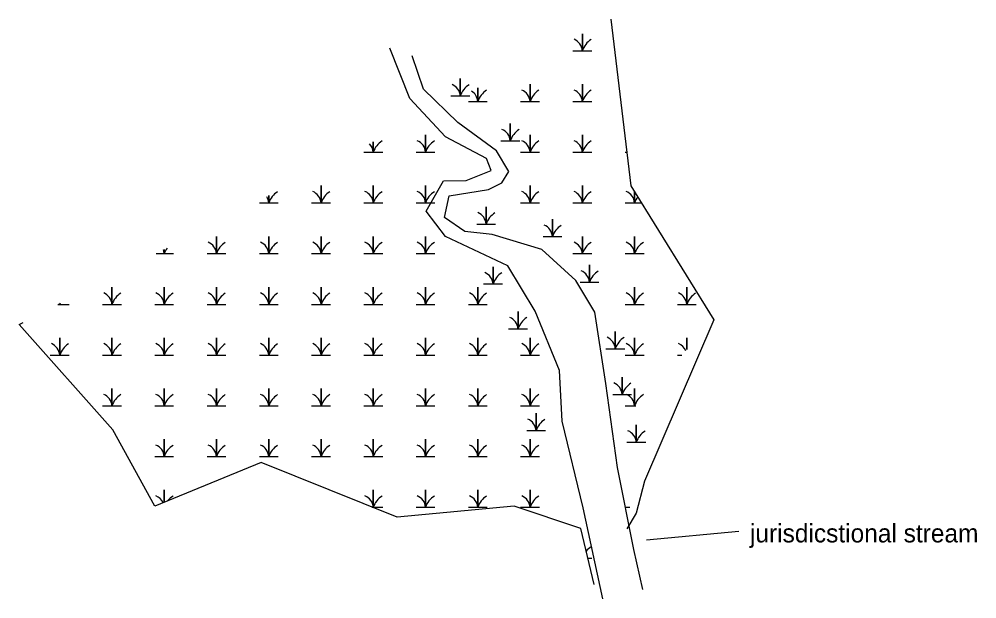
# Model space of a CAD drawing. Extents: x 2171061 to 2188174, y 801741 to 821647.
# Drawn here: x 2177074.5 to 2177361.5, y 807942.3 to 808115.8 of the extents above; entities that cross this region are included whole.
import ezdxf

# ---------------------------------------------------------------- set-up
doc = ezdxf.new("R2010")
doc.units = 0
doc.layers.add('Exist Environmental Wetland Boundary', color=7, linetype='Continuous')
doc.layers.add('Exist Hydro Jurisdictional Stream or Body of Water Mitigable', color=7, linetype='Continuous')

msp = doc.modelspace()

# ---------------------------------------------------------------- linework, layer by layer
at = {"layer": 'Exist Environmental Wetland Boundary'}
for points in [[(2177251.87, 808115.78), (2177257.81, 808065.93), (2177282.69, 808025.78), (2177261.9, 807977.45), (2177259.44, 807967.95), (2177256.66, 807963.24)], [(2177240.47, 808106.33), (2177243.29, 808106.33), (2177243.29, 808111.35)], [(2177243.29, 808111.35), (2177243.29, 808106.33), (2177246.11, 808106.33)], [(2177203.91, 808092.79), (2177206.73, 808092.79), (2177206.73, 808097.97), (2177206.73, 808092.79), (2177209.55, 808092.79)], [(2177209.15, 808091.14), (2177211.97, 808091.14), (2177211.97, 808095.22)], [(2177211.97, 808095.22), (2177211.97, 808091.14), (2177214.79, 808091.14)], [(2177224.81, 808091.14), (2177227.63, 808091.14), (2177227.63, 808096.32), (2177227.63, 808091.14), (2177230.45, 808091.14)], [(2177240.47, 808091.14), (2177243.29, 808091.14), (2177243.29, 808096.32), (2177243.29, 808091.14), (2177246.11, 808091.14)], [(2177218.87, 808079.36), (2177221.69, 808079.36), (2177221.69, 808084.54), (2177221.69, 808079.36), (2177224.52, 808079.36)], [(2177193.49, 808075.96), (2177196.31, 808075.96), (2177196.31, 808081.14), (2177196.31, 808075.96), (2177199.13, 808075.96)], [(2177224.81, 808075.96), (2177227.63, 808075.96), (2177227.63, 808081.14), (2177227.63, 808075.96), (2177230.45, 808075.96)], [(2177240.47, 808075.96), (2177243.29, 808075.96), (2177243.29, 808081.14), (2177243.29, 808075.96), (2177246.11, 808075.96)], [(2177177.83, 808075.96), (2177180.65, 808075.96), (2177180.65, 808079.08)], [(2177180.65, 808079.08), (2177180.65, 808075.96), (2177183.47, 808075.96)], [(2177256.13, 808075.96), (2177256.61, 808075.96)], [(2177162.17, 808060.78), (2177164.99, 808060.78), (2177164.99, 808065.95), (2177164.99, 808060.78), (2177167.81, 808060.78)], [(2177177.83, 808060.78), (2177180.65, 808060.78), (2177180.65, 808065.95), (2177180.65, 808060.78), (2177183.47, 808060.78)], [(2177193.49, 808060.78), (2177196.31, 808060.78), (2177196.31, 808065.95), (2177196.31, 808060.78), (2177199.13, 808060.78)], [(2177224.81, 808060.78), (2177227.63, 808060.78), (2177227.63, 808065.95), (2177227.63, 808060.78), (2177230.45, 808060.78)], [(2177240.47, 808060.78), (2177243.29, 808060.78), (2177243.29, 808065.95), (2177243.29, 808060.78), (2177246.11, 808060.78)], [(2177146.51, 808060.78), (2177149.33, 808060.78), (2177149.33, 808062.95)], [(2177149.33, 808062.95), (2177149.33, 808060.78), (2177152.15, 808060.78)], [(2177256.13, 808060.78), (2177258.95, 808060.78), (2177258.95, 808064.09)], [(2177258.95, 808064.09), (2177258.95, 808060.78), (2177261, 808060.78)], [(2177211.67, 808054.46), (2177214.49, 808054.46), (2177214.49, 808059.64), (2177214.49, 808054.46), (2177217.31, 808054.46)], [(2177231.52, 808050.71), (2177234.34, 808050.71), (2177234.34, 808055.88), (2177234.34, 808050.71), (2177237.16, 808050.71)], [(2177130.85, 808045.59), (2177133.67, 808045.59), (2177133.67, 808050.77), (2177133.67, 808045.59), (2177136.49, 808045.59)], [(2177146.51, 808045.59), (2177149.33, 808045.59), (2177149.33, 808050.77), (2177149.33, 808045.59), (2177152.15, 808045.59)], [(2177162.17, 808045.59), (2177164.99, 808045.59), (2177164.99, 808050.77), (2177164.99, 808045.59), (2177167.81, 808045.59)], [(2177177.83, 808045.59), (2177180.65, 808045.59), (2177180.65, 808050.77), (2177180.65, 808045.59), (2177183.47, 808045.59)], [(2177193.49, 808045.59), (2177196.31, 808045.59), (2177196.31, 808050.77), (2177196.31, 808045.59), (2177199.13, 808045.59)], [(2177240.47, 808045.59), (2177243.29, 808045.59), (2177243.29, 808050.77), (2177243.29, 808045.59), (2177246.11, 808045.59)], [(2177256.13, 808045.59), (2177258.95, 808045.59), (2177258.95, 808050.77), (2177258.95, 808045.59), (2177261.77, 808045.59)], [(2177115.64, 808045.59), (2177118.01, 808045.59), (2177118.01, 808046.82)], [(2177118.01, 808046.82), (2177118.01, 808045.59), (2177120.84, 808045.59)], [(2177213.71, 808036.51), (2177216.53, 808036.51), (2177216.53, 808041.69), (2177216.53, 808036.51), (2177219.36, 808036.51)], [(2177242.61, 808037.02), (2177245.43, 808037.02), (2177245.43, 808042.2), (2177245.43, 808037.02), (2177248.25, 808037.02)], [(2177099.53, 808030.41), (2177102.35, 808030.41), (2177102.35, 808035.59), (2177102.35, 808030.41), (2177105.18, 808030.41)], [(2177115.19, 808030.41), (2177118.01, 808030.41), (2177118.01, 808035.59), (2177118.01, 808030.41), (2177120.84, 808030.41)], [(2177130.85, 808030.41), (2177133.67, 808030.41), (2177133.67, 808035.59), (2177133.67, 808030.41), (2177136.49, 808030.41)], [(2177146.51, 808030.41), (2177149.33, 808030.41), (2177149.33, 808035.59), (2177149.33, 808030.41), (2177152.15, 808030.41)], [(2177162.17, 808030.41), (2177164.99, 808030.41), (2177164.99, 808035.59), (2177164.99, 808030.41), (2177167.81, 808030.41)], [(2177177.83, 808030.41), (2177180.65, 808030.41), (2177180.65, 808035.59), (2177180.65, 808030.41), (2177183.47, 808030.41)], [(2177193.49, 808030.41), (2177196.31, 808030.41), (2177196.31, 808035.59), (2177196.31, 808030.41), (2177199.13, 808030.41)], [(2177209.15, 808030.41), (2177211.97, 808030.41), (2177211.97, 808035.59), (2177211.97, 808030.41), (2177214.79, 808030.41)], [(2177256.13, 808030.41), (2177258.95, 808030.41), (2177258.95, 808035.59), (2177258.95, 808030.41), (2177261.77, 808030.41)], [(2177271.79, 808030.41), (2177274.61, 808030.41), (2177274.61, 808035.59), (2177274.61, 808030.41), (2177277.43, 808030.41)], [(2177086.16, 808030.41), (2177086.69, 808030.41), (2177086.69, 808030.68)], [(2177086.69, 808030.68), (2177086.69, 808030.41), (2177089.52, 808030.41)], [(2177221.19, 808023.08), (2177224.02, 808023.08), (2177224.02, 808028.26), (2177224.02, 808023.08), (2177226.84, 808023.08)], [(2177246.81, 807946.58), (2177242.88, 807963.33), (2177222.88, 807970.03), (2177187.78, 807966.67), (2177147.02, 807983.05), (2177115.16, 807969.99), (2177102.58, 807992.82), (2177074.55, 808024.42), (2177075.7, 808025.02)], [(2177250.35, 808017.15), (2177253.17, 808017.15), (2177253.17, 808022.32), (2177253.17, 808017.15), (2177256, 808017.15)], [(2177083.87, 808015.22), (2177086.69, 808015.22), (2177086.69, 808020.4), (2177086.69, 808015.22), (2177089.52, 808015.22)], [(2177099.53, 808015.22), (2177102.35, 808015.22), (2177102.35, 808020.4), (2177102.35, 808015.22), (2177105.18, 808015.22)], [(2177115.19, 808015.22), (2177118.01, 808015.22), (2177118.01, 808020.4), (2177118.01, 808015.22), (2177120.84, 808015.22)], [(2177130.85, 808015.22), (2177133.67, 808015.22), (2177133.67, 808020.4), (2177133.67, 808015.22), (2177136.49, 808015.22)], [(2177146.51, 808015.22), (2177149.33, 808015.22), (2177149.33, 808020.4), (2177149.33, 808015.22), (2177152.15, 808015.22)], [(2177162.17, 808015.22), (2177164.99, 808015.22), (2177164.99, 808020.4), (2177164.99, 808015.22), (2177167.81, 808015.22)], [(2177177.83, 808015.22), (2177180.65, 808015.22), (2177180.65, 808020.4), (2177180.65, 808015.22), (2177183.47, 808015.22)], [(2177193.49, 808015.22), (2177196.31, 808015.22), (2177196.31, 808020.4), (2177196.31, 808015.22), (2177199.13, 808015.22)], [(2177209.15, 808015.22), (2177211.97, 808015.22), (2177211.97, 808020.4), (2177211.97, 808015.22), (2177214.79, 808015.22)], [(2177224.81, 808015.22), (2177227.63, 808015.22), (2177227.63, 808020.4), (2177227.63, 808015.22), (2177230.45, 808015.22)], [(2177256.13, 808015.22), (2177258.95, 808015.22), (2177258.95, 808020.4), (2177258.95, 808015.22), (2177261.77, 808015.22)], [(2177274.61, 808016.88), (2177274.61, 808020.4), (2177274.61, 808016.88)], [(2177271.79, 808015.22), (2177273.1, 808015.22)], [(2177252.42, 808003.46), (2177255.24, 808003.46), (2177255.24, 808008.64), (2177255.24, 808003.46), (2177258.06, 808003.46)], [(2177099.53, 808000.04), (2177102.35, 808000.04), (2177102.35, 808005.22), (2177102.35, 808000.04), (2177105.18, 808000.04)], [(2177115.19, 808000.04), (2177118.01, 808000.04), (2177118.01, 808005.22), (2177118.01, 808000.04), (2177120.84, 808000.04)], [(2177130.85, 808000.04), (2177133.67, 808000.04), (2177133.67, 808005.22), (2177133.67, 808000.04), (2177136.49, 808000.04)], [(2177146.51, 808000.04), (2177149.33, 808000.04), (2177149.33, 808005.22), (2177149.33, 808000.04), (2177152.15, 808000.04)], [(2177162.17, 808000.04), (2177164.99, 808000.04), (2177164.99, 808005.22), (2177164.99, 808000.04), (2177167.81, 808000.04)], [(2177177.83, 808000.04), (2177180.65, 808000.04), (2177180.65, 808005.22), (2177180.65, 808000.04), (2177183.47, 808000.04)], [(2177193.49, 808000.04), (2177196.31, 808000.04), (2177196.31, 808005.22), (2177196.31, 808000.04), (2177199.13, 808000.04)], [(2177209.15, 808000.04), (2177211.97, 808000.04), (2177211.97, 808005.22), (2177211.97, 808000.04), (2177214.79, 808000.04)], [(2177224.81, 808000.04), (2177227.63, 808000.04), (2177227.63, 808005.22), (2177227.63, 808000.04), (2177230.45, 808000.04)], [(2177256.13, 808000.04), (2177258.95, 808000.04), (2177258.95, 808005.22), (2177258.95, 808000.04), (2177259.3, 808000.04)], [(2177226.61, 807992.62), (2177229.44, 807992.62), (2177229.44, 807997.8), (2177229.44, 807992.62), (2177232.26, 807992.62)], [(2177256.63, 807989.14), (2177259.45, 807989.14), (2177259.45, 807994.32), (2177259.45, 807989.14), (2177262.28, 807989.14)], [(2177115.19, 807984.86), (2177118.01, 807984.86), (2177118.01, 807990.03), (2177118.01, 807984.86), (2177120.84, 807984.86)], [(2177130.85, 807984.86), (2177133.67, 807984.86), (2177133.67, 807990.03), (2177133.67, 807984.86), (2177136.49, 807984.86)], [(2177146.51, 807984.86), (2177149.33, 807984.86), (2177149.33, 807990.03), (2177149.33, 807984.86), (2177152.15, 807984.86)], [(2177162.17, 807984.86), (2177164.99, 807984.86), (2177164.99, 807990.03), (2177164.99, 807984.86), (2177167.81, 807984.86)], [(2177177.83, 807984.86), (2177180.65, 807984.86), (2177180.65, 807990.03), (2177180.65, 807984.86), (2177183.47, 807984.86)], [(2177193.49, 807984.86), (2177196.31, 807984.86), (2177196.31, 807990.03), (2177196.31, 807984.86), (2177199.13, 807984.86)], [(2177209.15, 807984.86), (2177211.97, 807984.86), (2177211.97, 807990.03), (2177211.97, 807984.86), (2177214.79, 807984.86)], [(2177224.81, 807984.86), (2177227.63, 807984.86), (2177227.63, 807990.03), (2177227.63, 807984.86), (2177230.45, 807984.86)], [(2177118.01, 807971.16), (2177118.01, 807974.85), (2177118.01, 807971.16)], [(2177180.32, 807969.67), (2177180.65, 807969.67), (2177180.65, 807974.85), (2177180.65, 807969.67), (2177183.47, 807969.67)], [(2177193.49, 807969.67), (2177196.31, 807969.67), (2177196.31, 807974.85), (2177196.31, 807969.67), (2177199.13, 807969.67)], [(2177209.15, 807969.67), (2177211.97, 807969.67), (2177211.97, 807974.85), (2177211.97, 807969.67), (2177214.79, 807969.67)], [(2177224.81, 807969.67), (2177227.63, 807969.67), (2177227.63, 807974.85), (2177227.63, 807969.67), (2177230.45, 807969.67)], [(2177256.13, 807969.67), (2177257.53, 807969.67)], [(2177244.96, 807954.49), (2177246.11, 807954.49)]]:
    msp.add_lwpolyline(points, dxfattribs=at)
for centre, radius, start, end in [((2177239.26, 808106.04), 4.03, 4.1403, 67.535), ((2177249.27, 808104.34), 6.31, 122.1274, 161.6222), ((2177202.7, 808092.5), 4.03, 4.1403, 67.535), ((2177212.71, 808090.8), 6.31, 122.1274, 161.6222), ((2177207.95, 808090.85), 4.03, 4.1403, 57.6127), ((2177217.95, 808089.15), 6.31, 122.1274, 161.6222), ((2177223.6, 808090.85), 4.03, 4.1403, 67.535), ((2177233.61, 808089.15), 6.31, 122.1274, 161.6222), ((2177239.26, 808090.85), 4.03, 4.1403, 67.535), ((2177249.27, 808089.15), 6.31, 122.1274, 161.6222), ((2177217.67, 808079.07), 4.03, 4.1403, 67.535), ((2177227.68, 808077.38), 6.31, 122.1274, 161.6222), ((2177176.63, 808075.67), 4.03, 4.1403, 44.4732), ((2177186.64, 808073.97), 6.31, 122.1274, 161.6222), ((2177192.29, 808075.67), 4.03, 4.1403, 67.535), ((2177202.3, 808073.97), 6.31, 122.1274, 161.6222), ((2177223.6, 808075.67), 4.03, 4.1403, 67.535), ((2177233.61, 808073.97), 6.31, 122.1274, 161.6222), ((2177239.26, 808075.67), 4.03, 4.1403, 67.535), ((2177249.27, 808073.97), 6.31, 122.1274, 161.6222), ((2177145.31, 808060.48), 4.03, 4.1403, 32.2245), ((2177155.32, 808058.79), 6.31, 122.1274, 161.6222), ((2177160.97, 808060.48), 4.03, 4.1403, 67.535), ((2177170.98, 808058.79), 6.31, 122.1274, 161.6222), ((2177176.63, 808060.48), 4.03, 4.1403, 67.535), ((2177186.64, 808058.79), 6.31, 122.1274, 161.6222), ((2177192.29, 808060.48), 4.03, 4.1403, 67.535), ((2177202.3, 808058.79), 6.31, 122.1274, 161.6222), ((2177223.6, 808060.48), 4.03, 4.1403, 67.535), ((2177233.61, 808058.79), 6.31, 122.1274, 161.6222), ((2177239.26, 808060.48), 4.03, 4.1403, 67.535), ((2177249.27, 808058.79), 6.31, 122.1274, 161.6222), ((2177254.92, 808060.48), 4.03, 4.1403, 67.535), ((2177264.93, 808058.79), 6.31, 143.128, 161.6222), ((2177210.46, 808054.17), 4.03, 4.1403, 67.535), ((2177220.47, 808052.47), 6.31, 122.1274, 161.6222), ((2177230.31, 808050.42), 4.03, 4.1403, 67.535), ((2177240.32, 808048.72), 6.31, 122.1274, 161.6222), ((2177129.65, 808045.3), 4.03, 4.1403, 67.535), ((2177139.66, 808043.6), 6.31, 122.1274, 161.6222), ((2177145.31, 808045.3), 4.03, 4.1403, 67.535), ((2177155.32, 808043.6), 6.31, 122.1274, 161.6222), ((2177160.97, 808045.3), 4.03, 4.1403, 67.535), ((2177170.98, 808043.6), 6.31, 122.1274, 161.6222), ((2177176.63, 808045.3), 4.03, 4.1403, 67.535), ((2177186.64, 808043.6), 6.31, 122.1274, 161.6222), ((2177192.29, 808045.3), 4.03, 4.1403, 67.535), ((2177202.3, 808043.6), 6.31, 122.1274, 161.6222), ((2177239.26, 808045.3), 4.03, 4.1403, 67.535), ((2177249.27, 808043.6), 6.31, 122.1274, 161.6222), ((2177254.92, 808045.3), 4.03, 4.1403, 67.535), ((2177264.93, 808043.6), 6.31, 122.1274, 161.6222), ((2177113.99, 808045.3), 4.03, 4.1403, 20.2035), ((2177124, 808043.6), 6.31, 144.6947, 161.6222), ((2177212.51, 808036.22), 4.03, 4.1403, 67.535), ((2177222.52, 808034.52), 6.31, 122.1274, 161.6222), ((2177241.41, 808036.73), 4.03, 4.1403, 67.535), ((2177251.42, 808035.04), 6.31, 122.1274, 161.6222), ((2177098.33, 808030.12), 4.03, 4.1403, 67.535), ((2177113.99, 808030.12), 4.03, 4.1403, 67.535), ((2177129.65, 808030.12), 4.03, 4.1403, 67.535), ((2177145.31, 808030.12), 4.03, 4.1403, 67.535), ((2177160.97, 808030.12), 4.03, 4.1403, 67.535), ((2177176.63, 808030.12), 4.03, 4.1403, 67.535), ((2177192.29, 808030.12), 4.03, 4.1403, 67.535), ((2177207.95, 808030.12), 4.03, 4.1403, 67.535), ((2177254.92, 808030.12), 4.03, 4.1403, 67.535), ((2177270.58, 808030.12), 4.03, 4.1403, 67.535), ((2177108.34, 808028.42), 6.31, 122.1274, 161.6222), ((2177124, 808028.42), 6.31, 122.1274, 161.6222), ((2177139.66, 808028.42), 6.31, 122.1274, 161.6222), ((2177155.32, 808028.42), 6.31, 122.1274, 161.6222), ((2177170.98, 808028.42), 6.31, 122.1274, 161.6222), ((2177186.64, 808028.42), 6.31, 122.1274, 161.6222), ((2177202.3, 808028.42), 6.31, 122.1274, 161.6222), ((2177217.95, 808028.42), 6.31, 122.1274, 161.6222), ((2177264.93, 808028.42), 6.31, 122.1274, 161.6222), ((2177280.59, 808028.42), 6.31, 122.1274, 161.6222), ((2177082.67, 808030.12), 4.03, 4.1403, 7.8557), ((2177092.68, 808028.42), 6.31, 158.3578, 161.6222), ((2177219.99, 808022.79), 4.03, 4.1403, 67.535), ((2177230, 808021.1), 6.31, 122.1274, 161.6222), ((2177249.15, 808016.85), 4.03, 4.1403, 67.535), ((2177259.16, 808015.16), 6.31, 122.1274, 161.6222), ((2177082.67, 808014.93), 4.03, 4.1403, 67.535), ((2177092.68, 808013.24), 6.31, 122.1274, 161.6222), ((2177098.33, 808014.93), 4.03, 4.1403, 67.535), ((2177108.34, 808013.24), 6.31, 122.1274, 161.6222), ((2177113.99, 808014.93), 4.03, 4.1403, 67.535), ((2177124, 808013.24), 6.31, 122.1274, 161.6222), ((2177129.65, 808014.93), 4.03, 4.1403, 67.535), ((2177139.66, 808013.24), 6.31, 122.1274, 161.6222), ((2177145.31, 808014.93), 4.03, 4.1403, 67.535), ((2177155.32, 808013.24), 6.31, 122.1274, 161.6222), ((2177160.97, 808014.93), 4.03, 4.1403, 67.535), ((2177170.98, 808013.24), 6.31, 122.1274, 161.6222), ((2177176.63, 808014.93), 4.03, 4.1403, 67.535), ((2177186.64, 808013.24), 6.31, 122.1274, 161.6222), ((2177192.29, 808014.93), 4.03, 4.1403, 67.535), ((2177202.3, 808013.24), 6.31, 122.1274, 161.6222), ((2177207.95, 808014.93), 4.03, 4.1403, 67.535), ((2177217.95, 808013.24), 6.31, 122.1274, 161.6222), ((2177223.6, 808014.93), 4.03, 4.1403, 67.535), ((2177233.61, 808013.24), 6.31, 122.1274, 161.6222), ((2177254.92, 808014.93), 4.03, 4.1403, 67.535), ((2177264.93, 808013.24), 6.31, 122.1274, 161.6222), ((2177270.58, 808014.93), 4.03, 23.3397, 67.535), ((2177251.21, 808003.17), 4.03, 4.1403, 67.535), ((2177261.22, 808001.47), 6.31, 122.1274, 161.6222), ((2177098.33, 807999.75), 4.03, 4.1403, 67.535), ((2177108.34, 807998.05), 6.31, 122.1274, 161.6222), ((2177113.99, 807999.75), 4.03, 4.1403, 67.535), ((2177124, 807998.05), 6.31, 122.1274, 161.6222), ((2177129.65, 807999.75), 4.03, 4.1403, 67.535), ((2177139.66, 807998.05), 6.31, 122.1274, 161.6222), ((2177145.31, 807999.75), 4.03, 4.1403, 67.535), ((2177155.32, 807998.05), 6.31, 122.1274, 161.6222), ((2177160.97, 807999.75), 4.03, 4.1403, 67.535), ((2177170.98, 807998.05), 6.31, 122.1274, 161.6222), ((2177176.63, 807999.75), 4.03, 4.1403, 67.535), ((2177186.64, 807998.05), 6.31, 122.1274, 161.6222), ((2177192.29, 807999.75), 4.03, 4.1403, 67.535), ((2177202.3, 807998.05), 6.31, 122.1274, 161.6222), ((2177207.95, 807999.75), 4.03, 4.1403, 67.535), ((2177217.95, 807998.05), 6.31, 122.1274, 161.6222), ((2177223.6, 807999.75), 4.03, 4.1403, 67.535), ((2177233.61, 807998.05), 6.31, 122.1274, 161.6222), ((2177254.92, 807999.75), 4.03, 4.1403, 67.535), ((2177264.93, 807998.05), 6.31, 122.1274, 161.6222), ((2177225.41, 807992.33), 4.03, 4.1403, 67.535), ((2177235.42, 807990.63), 6.31, 122.1274, 161.6222), ((2177255.43, 807988.85), 4.03, 4.1403, 67.535), ((2177265.44, 807987.15), 6.31, 122.1274, 161.6222), ((2177113.99, 807984.57), 4.03, 4.1403, 67.535), ((2177124, 807982.87), 6.31, 122.1274, 161.6222), ((2177129.65, 807984.57), 4.03, 4.1403, 67.535), ((2177139.66, 807982.87), 6.31, 122.1274, 161.6222), ((2177145.31, 807984.57), 4.03, 4.1403, 67.535), ((2177155.32, 807982.87), 6.31, 122.1274, 161.6222), ((2177160.97, 807984.57), 4.03, 4.1403, 67.535), ((2177170.98, 807982.87), 6.31, 122.1274, 161.6222), ((2177176.63, 807984.57), 4.03, 4.1403, 67.535), ((2177186.64, 807982.87), 6.31, 122.1274, 161.6222), ((2177192.29, 807984.57), 4.03, 4.1403, 67.535), ((2177202.3, 807982.87), 6.31, 122.1274, 161.6222), ((2177207.95, 807984.57), 4.03, 4.1403, 67.535), ((2177217.95, 807982.87), 6.31, 122.1274, 161.6222), ((2177223.6, 807984.57), 4.03, 4.1403, 67.535), ((2177233.61, 807982.87), 6.31, 122.1274, 161.6222), ((2177113.99, 807969.38), 4.03, 23.9211, 67.535), ((2177124, 807967.69), 6.31, 122.1274, 141.9253), ((2177176.63, 807969.38), 4.03, 4.1403, 67.535), ((2177186.64, 807967.69), 6.31, 122.1274, 161.6222), ((2177192.29, 807969.38), 4.03, 4.1403, 67.535), ((2177202.3, 807967.69), 6.31, 122.1274, 161.6222), ((2177207.95, 807969.38), 4.03, 4.1403, 67.535), ((2177217.95, 807967.69), 6.31, 122.1274, 161.6222), ((2177223.6, 807969.38), 4.03, 4.1403, 67.535), ((2177233.61, 807967.69), 6.31, 122.1274, 161.6222), ((2177249.27, 807952.5), 6.31, 122.1274, 139.6773)]:
    msp.add_arc(centre, radius, start, end, dxfattribs=at)
at = {"layer": 'Exist Hydro Jurisdictional Stream or Body of Water Mitigable'}
msp.add_line((2177290.19, 807962.39), (2177262.47, 807959.81), dxfattribs=at)
for points in [[(2177249.42, 807942.27), (2177243.53, 807969.53), (2177237.24, 807995.41), (2177236.4, 808010.65), (2177229.17, 808028.42), (2177220.97, 808041.98), (2177202.33, 808050.71), (2177196.45, 808058.32), (2177201.67, 808067.42), (2177208.53, 808067.52), (2177215.94, 808070.48), (2177214.61, 808074.07), (2177202.27, 808080.59), (2177191.6, 808091.99), (2177185.65, 808107.06)], [(2177261.46, 807945.03), (2177258.67, 807957.05), (2177253.81, 807981.61), (2177250.31, 808006.75), (2177247.05, 808028.05), (2177241.32, 808037.55), (2177231.11, 808046.88), (2177216.28, 808051.35), (2177208.12, 808052.26), (2177202.04, 808056.39), (2177203.38, 808062.86), (2177215.19, 808064.83), (2177219.14, 808066.74), (2177221.27, 808070.18), (2177217.53, 808076.36), (2177205.95, 808084.8), (2177195.74, 808094.82), (2177192.35, 808104.79)]]:
    msp.add_lwpolyline(points, dxfattribs=at)

# ---------------------------------------------------------------- texts
msp.add_text('jurisdicstional stream', height=5.4837, dxfattribs=at).set_placement((2177293.51, 807959.16))

doc.saveas('drawing.dxf')
